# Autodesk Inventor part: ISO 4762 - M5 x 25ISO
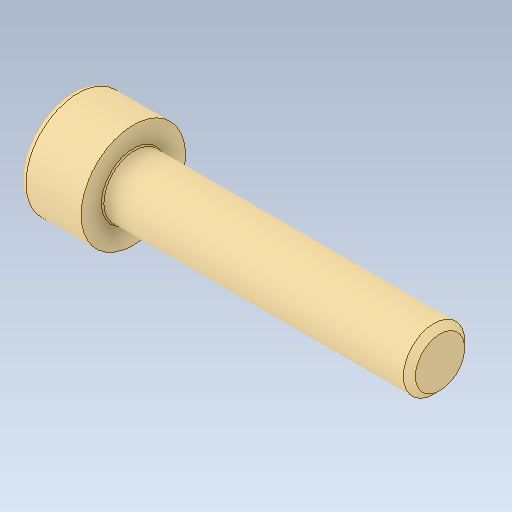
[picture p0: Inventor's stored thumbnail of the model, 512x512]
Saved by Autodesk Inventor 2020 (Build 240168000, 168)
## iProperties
Created: 2015-11
Part Number: ISO 4762 - M5 x 25ISO
Material: Ogólny
Document SubType Name: Modeling
Designer: Tomasz
Density: 1 g/cm^3
Appearance: Domyślna
Sending System: SolidWorks 2017
Last Author: Tomasz
Last Saved: 2017-11-20
Author: Tomasz
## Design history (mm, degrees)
feature "Imported1"
node "Bryła1"
